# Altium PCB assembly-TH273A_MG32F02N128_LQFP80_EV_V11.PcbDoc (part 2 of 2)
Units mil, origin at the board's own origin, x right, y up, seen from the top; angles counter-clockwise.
Board outline 4724.41 x 2637.8 mil, 2 copper layers (Top Layer, Bottom Layer); 182 components, 166 nets, 741 pads, 331 vias.
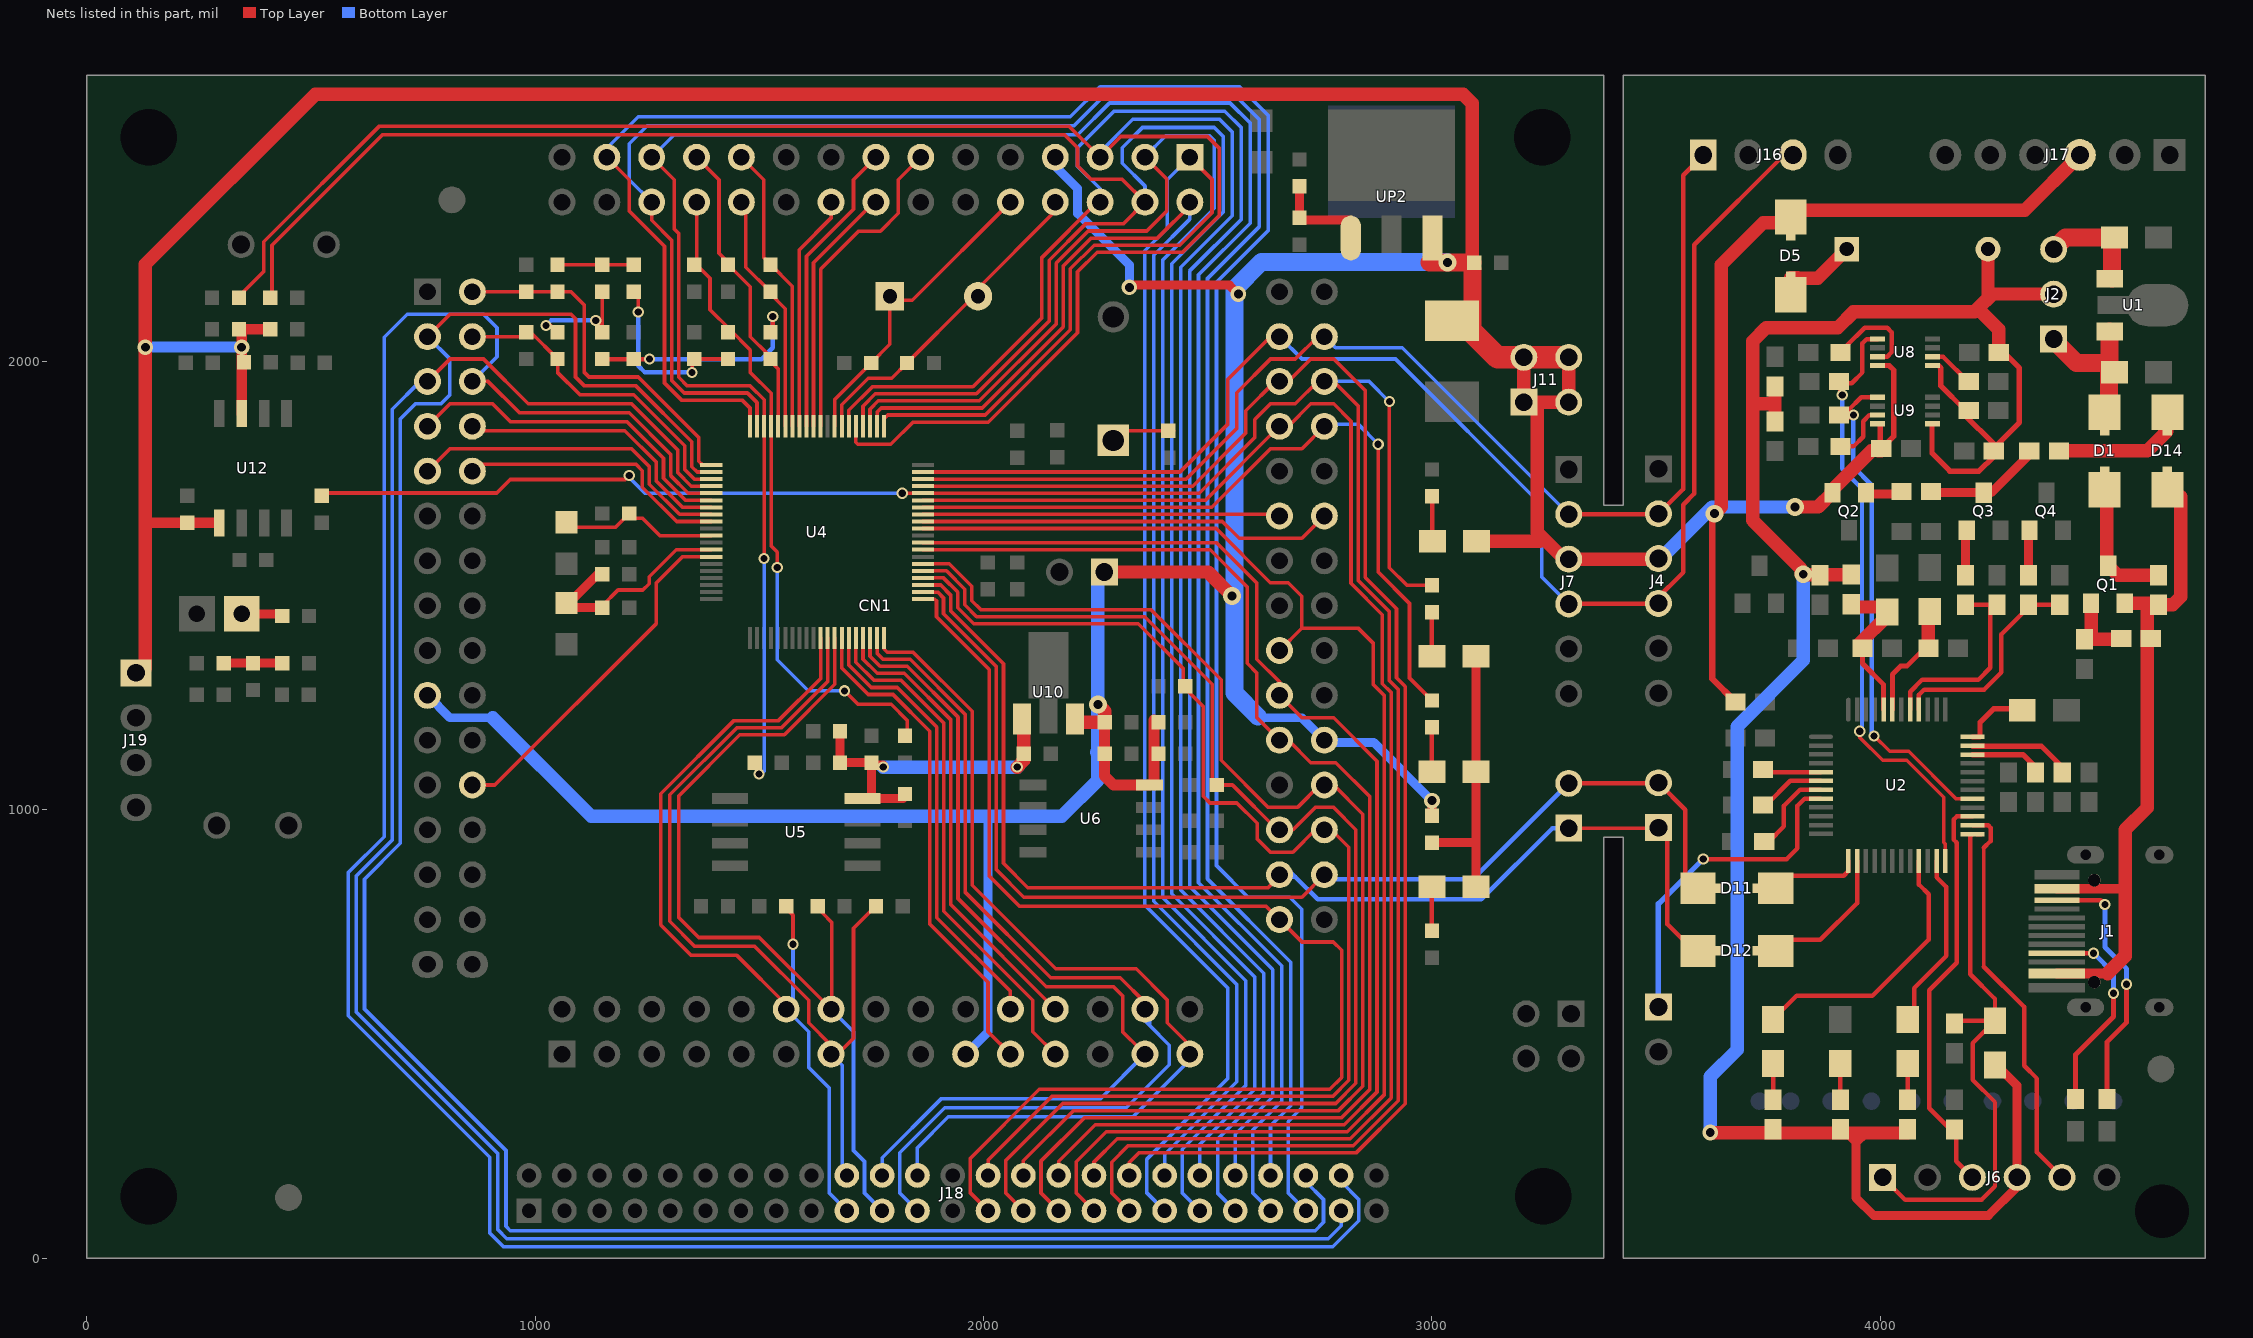
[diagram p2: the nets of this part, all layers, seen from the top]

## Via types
v1: diameter 20, hole 12, Top Layer to Bottom Layer, tented both sides, 236 vias
v2: diameter 25, hole 16, Top Layer to Bottom Layer, tented both sides, 57 vias
v3: diameter 30, hole 12, Top Layer to Bottom Layer, tented both sides, 13 vias
v4: diameter 35, hole 20, Top Layer to Bottom Layer, tented both sides, 8 vias
v5: diameter 40, hole 20, Top Layer to Bottom Layer, tented both sides, 7 vias
v6: diameter 25, hole 12, Top Layer to Bottom Layer, tented both sides, 6 vias
v7: diameter 30, hole 16, Top Layer to Bottom Layer, tented both sides, 2 vias
v8: diameter 28, hole 16, Top Layer to Bottom Layer, tented both sides, 1 vias
v9: diameter 15, hole 12, Top Layer to Bottom Layer, tented both sides, 1 vias

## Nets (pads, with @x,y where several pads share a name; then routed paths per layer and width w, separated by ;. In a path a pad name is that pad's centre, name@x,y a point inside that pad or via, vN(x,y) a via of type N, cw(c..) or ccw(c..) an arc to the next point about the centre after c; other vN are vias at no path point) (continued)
LCD_P16: CN1.12 J18.19 R52.1 U4.11 | length 1965.9
  Top Layer w8: R52.1@1552.42,777.5 1559.92,777.5 1562.42,777.5 1574.92,765 v2(1574.92,700) ; CN1.12@1559.92,565 1449.92,675 1347.91,675 1279.92,742.99 1279.92,1035.25 1443.43,1198.75 1542.83,1198.75 1636.54,1292.46 U4.11@1636.54,1382.91
  Bottom Layer w8: CN1.12@1574.92,560 1569.92,555 CN1.12@1559.92,555 ; v2(1574.92,700) 1574.92,570 CN1.12@1559.92,555 ; J18.19@1695.04,105.63 1655.67,145 1655.67,379.25 1609.92,425 1609.92,505 CN1.12@1559.92,555
LCD_P17: CN1.13 J18.20 R49.1 U4.12 | length 2044.5
  Top Layer w8: U4.12@1652.28,1382.91 1652.28,1285.93 1549.35,1183 1449.95,1183 1299.92,1032.98 1299.92,751.27 1356.2,695 1489.92,695 1609.92,575 1609.92,525 1659.92,475 CN1.13@1659.92,455 ; CN1.13@1674.92,455 1709.92,490 1709.92,735.41 1754.51,780 1759.92,780 1764.92,780 R49.1@1769.92,785
  Bottom Layer w8: CN1.13@1659.92,430.71 CN1.13@1659.92,455 1684.92,430 1684.92,194.49 J18.20@1695.04,184.37
LCD_P18: CN1.14 J18.21 R50.1 U4.13 | length 1979.7
  Top Layer w8: R50.1@1639.92,785 1639.92,770 1661.56,748.36 CN1.14@1661.56,556.64 ; CN1.14@1656.64,558.28 1499.92,715 1364.48,715 1319.92,759.56 1319.92,1030.71 1456.47,1167.26 1555.88,1167.26 1668.03,1279.41 U4.13@1668.03,1382.91
  Bottom Layer w8: CN1.14@1659.92,555 1709.92,505 1709.92,240 1734.41,215.51 1734.41,145 J18.21@1773.78,105.63
LCD_P19: CN1.27 J18.22 U4.18 | length 2013.1
  Top Layer w8: U4.18@1746.77,1382.91 1746.77,1342.1 1769.11,1319.76 1829.7,1319.76 1942.91,1206.55 1942.91,802.01 2139.92,605 2289.92,605 2309.92,585 2309.92,505 CN1.27@2350.36,464.56
  Bottom Layer w8: J18.22@1773.78,184.37 1773.78,223.86 1904.92,355 2259.92,355 CN1.27@2359.92,455
LCD_P20: CN1.28 J18.23 U4.19 | length 2176.1
  Top Layer w8: U4.19@1762.52,1382.91 1762.52,1348.62 1775.63,1335.51 1836.22,1335.51 1958.66,1213.07 1958.66,816.26 2149.92,625 2304.92,625 2359.92,570 CN1.28@2359.92,555
  Bottom Layer w8: J18.23@1852.52,105.63 1813.15,145 1813.15,234.94 1913.21,335 2318.11,335 2414.37,431.26 2414.37,475 2369.92,519.45 ; CN1.28@2359.92,529.45 2369.92,519.45 ; CN1.28@2369.92,545 2369.92,519.45
LCD_P21: CN1.29 J18.24 U4.20 | length 2093.6
  Top Layer w8: U4.20@1778.27,1382.91 1778.27,1357.87 1784.88,1351.26 1842.75,1351.26 1974.41,1219.6 1974.41,831.22 2160.63,645 2340.43,645 2409.92,575.51 2409.92,525 CN1.29@2459.92,475 ; CN1.29@2459.92,454.29 CN1.29@2459.92,455
  Bottom Layer w8: J18.24@1852.52,184.37 1852.52,246.16 1921.36,315 2333.11,315 2459.92,441.81 CN1.29@2459.92,455
LCD_P22: CN1.32 J18.27 U4.21 | length 2867.9
  Top Layer w8: U4.21@1864.88,1469.53 1891.1,1469.53 1894.92,1465.71 1894.92,1430.46 2012.87,1312.51 2012.87,852.05 2079.92,785 2629.92,785 CN1.32@2659.92,755 2709.92,705 2779.92,705 2798.62,686.3 2798.62,402.88 2772,376.26 2124.37,376.26 1970.63,222.52 1970.63,145 J18.27@2010,105.63
LCD_P23: CN1.35 J18.28 R47.1 U4.24 | length 2862.9
  Top Layer w8: U4.24@1864.88,1516.77 1910.67,1516.77 1942.17,1485.28 1942.17,1450.48 1977.89,1414.76 2345.16,1414.76 2445.13,1314.8 R47.1@2445.13,1275 ; J18.28@2010,184.37 2010,218.23 2152.28,360.51 2778.52,360.51 2814.37,396.36 2814.37,916.3 2775.67,955 CN1.35@2759.92,955 2739.92,955 2689.92,905 2639.92,905 2610.33,934.59 2610.33,969.59 2564.92,1015 2504.92,1015 2489.92,1030 2489.92,1230.2 2447.52,1272.6 R47.1@2445.13,1275 ; R47.1@2445.13,1284.8 R47.1@2445.13,1275
LCD_P24: CN1.36 J18.29 R46.1 U4.25 | length 2938.9
  Top Layer w8: U4.25@1864.88,1532.52 1917.19,1532.52 1957.91,1491.8 1957.91,1457.01 1984.41,1430.51 2359.41,1430.51 2509.92,1280 2509.92,1055 R46.1@2519.92,1055 ; J18.29@2088.74,105.63 2049.37,145 2049.37,217.6 2176.54,344.76 2785.05,344.76 2830.12,389.83 2830.12,955.51 2780.63,1005 2739.92,1005 2689.92,955 CN1.36@2659.92,955 2654.92,955 2554.92,1055 R46.1@2524.92,1055
LCD_P25: CN1.37 J18.30 U4.26 | length 2842.7
  Top Layer w8: U4.26@1864.88,1548.27 1923.72,1548.27 1973.66,1498.32 1973.66,1466.26 1993.66,1446.26 2373.15,1446.26 2529.92,1289.49 2529.92,1110 2634.92,1005 2699.92,1005 2749.92,1055 CN1.37@2759.92,1055 2780.63,1055 2845.87,989.76 2845.87,383.31 2791.57,329.02 2200.79,329.02 2088.74,216.97 J18.30@2088.74,184.37
LCD_P26: CN1.40 J18.31 U4.28 | length 2962.2
  Top Layer w8: U4.28@1864.88,1579.76 2505.16,1579.76 2588.16,1496.76 2588.16,1326.25 2609.41,1305 2609.41,1205.51 CN1.40@2659.92,1155 2679.92,1155 2729.92,1105 2785.63,1105 2861.61,1029.02 2861.61,376.79 2798.09,313.27 2225.04,313.27 2128.11,216.34 2128.11,145 J18.31@2167.48,105.63
LCD_P27: CN1.42 J18.32 U4.29 | length 2874.7
  Top Layer w8: U4.29@1864.88,1595.51 2519.41,1595.51 2609.37,1505.55 2609.37,1335.55 2659.92,1285 CN1.42@2659.92,1255 2709.92,1205 2780.63,1205 2877.36,1108.27 2877.36,370.27 2804.62,297.52 2249.29,297.52 2167.48,215.71 J18.32@2167.48,184.37
LCD_P28: CN1.44 J18.33 U4.31 | length 3113.4
  Top Layer w8: U4.31@1864.88,1627.01 2518.62,1627.01 2639.37,1506.26 2679.37,1506.26 2709.37,1476.26 2709.37,1404.45 ; J18.33@2246.22,105.63 2206.85,145 2206.85,215.08 2273.54,281.77 2811.14,281.77 2893.11,363.74 2893.11,1255 2869.37,1278.74 2869.37,1370.55 2834.92,1405 2709.92,1405 2709.37,1404.45 ; CN1.44@2659.92,1355 2709.37,1404.45
LCD_P29: CN1.54 J18.34 U4.35 | length 3357.6
  Top Layer w8: U4.35@1864.88,1690 2494.92,1690 2657.42,1852.5 2659.92,1852.5 2662.42,1852.5 2664.92,1855 2679.92,1855 2729.92,1905 2780.63,1905 2819.37,1866.26 2819.37,1504.92 2889.37,1434.92 2889.37,1281.01 2908.86,1261.52 2908.86,357.22 2817.66,266.02 2297.79,266.02 2246.22,214.45 J18.34@2246.22,184.37
LCD_P30: CN1.55 J18.35 R55.1 R91.1 U4.36 | length 5578.2
  Top Layer w8: R91.1@524.41,1706.26 914.37,1706.26 944.37,1736.26 1201.12,1736.26 v2(1209.86,1745) ; v2(1818.66,1705.75) U4.36@1864.88,1705.75 2480.67,1705.75 2604.92,1830 2604.92,1870 2639.92,1905 2694.92,1905 2744.92,1955 CN1.55@2759.92,1955 2780.63,1955 2835.12,1900.51 2835.12,1511.44 2905.12,1441.44 2905.12,1335 2905.12,1287.53 2924.61,1268.04 2924.61,350.7 2824.19,250.28 2322.05,250.28 2285.59,213.82 2285.59,145 J18.35@2324.96,105.63 ; v2(2904.92,1910) 2904.92,1539.49 2944.09,1500.32 R55.1@2999.96,1500.32 2958.39,1500.32
  Bottom Layer w8: v2@1214.41,1736.26 1244.92,1705.75 v2(1818.66,1705.75) ; CN1.55@2759.92,1955 2859.92,1955 v2(2904.92,1910)
LCD_P31: CN1.56 J18.36 U4.37 | length 3487.9
  Top Layer w8: U4.37@1864.88,1721.5 2466.42,1721.5 2584.92,1840 2584.92,1890 2649.92,1955 CN1.56@2659.92,1955 2679.72,1955 2729.72,2005 2780.63,2005 2850.87,1934.76 2850.87,1517.96 2920.87,1447.97 2920.87,1294.06 2940.35,1274.57 2940.35,344.17 2830.71,234.53 2346.3,234.53 2324.96,213.19 J18.36@2324.96,184.37
LCD_P32: CN1.61 J18.37 U4.41 | length 3720.9
  Top Layer w8: U4.41@1778.27,1855.35 1778.27,1872.16 1786.21,1880.1 2003.67,1880.1 2193.62,2070.05 2193.62,2205.97 2246.67,2259.02 2437.13,2259.02 2509.37,2331.26 2509.37,2405.55 CN1.61@2459.92,2455
  Bottom Layer w8: J18.37@2403.7,105.63 2364.33,145 2364.33,220.83 2544.92,401.42 2544.92,602.01 2359.37,787.56 2359.37,2246.26 2409.37,2296.26 2409.37,2404.45 CN1.61@2459.92,2455
LCD_P33: CN1.62 J18.38 U4.42 | length 3352.1
  Top Layer w8: U4.42@1762.52,1855.35 1762.52,1886.63 1771.74,1895.85 1997.15,1895.85 2177.87,2076.58 2177.87,2212.49 2240.14,2274.76 2387.87,2274.76 CN1.62@2464.02,2350.91
  Bottom Layer w8: J18.38@2403.7,184.37 2403.7,231.92 2564.92,393.14 2564.92,610.29 2379.37,795.85 2379.37,2236.26 2459.37,2316.26 CN1.62@2459.37,2355
LCD_P34: CN1.63 J18.39 U4.43 | length 3866.6
  Top Layer w8: U4.43@1746.77,1855.35 1746.77,1893.15 1765.22,1911.6 1990.62,1911.6 2162.13,2083.1 2162.13,2219.02 2233.62,2290.51 2363.62,2290.51 2408.37,2335.26 2408.37,2406.55 CN1.63@2359.92,2455
  Bottom Layer w8: CN1.63@2359.92,2456.74 2406.18,2503 2504.37,2503 2514.37,2493 2514.37,2340.97 2399.37,2225.97 2399.37,804.13 2584.92,618.58 2584.92,384.85 2443.07,243 2443.07,145 J18.39@2482.44,105.63
LCD_P35: CN1.64 J18.40 R89.1 U4.44 | length 6092.7
  Top Layer w8: R89.1@413.15,2141.26 413.15,2258.74 659.41,2505 2180.63,2505 2209.37,2476.26 2209.37,2436.26 2239.37,2406.26 2308.66,2406.26 CN1.64@2359.92,2355 2311.18,2306.26 2227.1,2306.26 2146.38,2225.54 2146.38,2089.62 1984.1,1927.35 1758.7,1927.35 1731.02,1899.67 U4.44@1731.02,1855.35
  Bottom Layer w8: CN1.64@2359.92,2341.81 CN1.64@2359.92,2355 2359.92,2390.71 2309.37,2441.26 2309.37,2476.26 2354.37,2521.26 2514.37,2521.26 2534.37,2501.26 2534.37,2332.68 2419.37,2217.68 2419.37,812.41 2604.92,626.86 2604.92,376.57 2482.44,254.09 J18.40@2482.44,184.37
LCD_P36: CN1.65 J18.41 R90.1 U4.45 | length 6737.5
  Top Layer w8: R90.1@337.52,2143.11 R90.1@339.37,2144.96 ; R90.1@339.37,2141.26 R90.1@339.37,2144.96 ; U4.45@1715.28,1855.35 1715.28,1819.65 1719.92,1815 1793.11,1815 1842.47,1864.36 2010.19,1864.36 2209.37,2063.53 2209.37,2199.45 2253.19,2243.27 2443.65,2243.27 2525.12,2324.74 2525.12,2475.55 2499.41,2501.26 2389.37,2501.26 ; 2324.37,2501.26 2389.37,2501.26 ; R90.1@339.37,2144.96 394.41,2200 394.41,2266.5 651.65,2523.74 2191.18,2523.74 CN1.65@2259.92,2455 2306.18,2501.26 2389.37,2501.26
  Bottom Layer w8: CN1.65@2259.92,2455 2259.92,2466.81 2332.63,2539.52 2526.11,2539.52 2554.37,2511.26 2554.37,2324.4 2439.37,2209.4 2439.37,820.7 2624.92,635.15 2624.92,368.28 2521.81,265.17 2521.81,145 J18.41@2561.18,105.63
LCD_P37: CN1.66 J18.42 U4.46 | length 3918.9
  Top Layer w8: U4.46@1699.53,1855.35 1699.53,1890.45 1752.18,1943.1 1976.21,1943.1 2130.12,2097.01 2130.12,2231.55 2253.57,2355 CN1.66@2259.92,2355
  Bottom Layer w8: CN1.66@2259.92,2355 2259.92,2385 2209.37,2435.55 2209.37,2476.26 2290.89,2557.78 2537.85,2557.78 2574.37,2521.26 2574.37,2316.11 2459.37,2201.11 2459.37,828.98 2644.92,643.43 2644.92,360 2561.18,276.26 J18.42@2561.18,184.37
LCD_P38: CN1.85 J18.43 R53.1 U4.58 | length 5585.5
  Top Layer w8: CN1.85@1259.92,2455 1309.92,2405 1309.92,2295 1319.92,2285 1319.92,1964.41 1339.33,1945 1479.92,1945 1510.55,1914.37 U4.58@1510.55,1855.35 v2(1510.55,1560) ; v2@1494.41,1079.41 R53.1@1494.41,1104.41
  Bottom Layer w8: CN1.85@1259.92,2455 1309.92,2505 2209.92,2505 2280.96,2576.04 2549.59,2576.04 2594.37,2531.26 2594.37,2307.83 2479.37,2192.83 2479.37,837.27 2664.92,651.72 2664.92,350 2600.55,285.63 2600.55,145 J18.43@2639.92,105.63 ; v2@1504.41,1079.41 1510.55,1085.55 v2(1510.55,1560)
  other v2: 1499.41,1079.41
LCD_P39: CN1.86 J18.44 U4.59 | length 4930.7
  Top Layer w8: CN1.86@1259.92,2355 1259.92,2314.25 1304.17,2270 1304.17,1957.88 1332.81,1929.25 1473.4,1929.25 1494.8,1907.85 U4.59@1494.8,1855.35
  Bottom Layer w8: CN1.86@1259.92,2355 1209.92,2405 1209.92,2485 1249.92,2525 1419.92,2525 ; 1289.92,2525 1419.92,2525 ; J18.44@2639.92,184.37 2639.92,295 2684.92,340 2684.92,660 2499.37,845.55 2499.37,2184.54 2614.37,2299.54 2614.37,2539.54 2559.61,2594.3 2270.94,2594.3 2201.64,2525 1419.92,2525
LCD_P40: CN1.87 J18.45 U4.60 | length 5071.3
  Top Layer w8: CN1.87@1159.92,2455 1209.92,2405 1209.92,2335 1288.43,2256.5 1288.43,1951.36 1326.28,1913.5 1461.42,1913.5 1479.05,1895.87 U4.60@1479.05,1855.35
  Bottom Layer w8: CN1.87@1159.92,2455 1159.92,2475 1229.92,2545 1299.92,2545 ; 1289.92,2545 1299.92,2545 ; J18.45@2704.92,119.37 J18.45@2718.66,105.63 2679.29,145 2679.29,304.43 2709.86,335 2709.86,778 2682.86,805 2589.86,805 2519.37,875.49 2519.37,2176.26 2634.37,2291.26 2634.37,2548.61 2570.42,2612.56 2260.91,2612.56 2193.35,2545 1299.92,2545
LCD_P41: CN1.93 J18.46 U4.62 | length 5097
  Top Layer w8: CN1.93@759.92,2055 809.92,2105 1079.92,2105 1089.92,2095 1089.92,1965 1109.92,1945 1224.92,1945 1349.17,1820.75 1349.17,1764.99 1361.17,1752.99 U4.62@1392.44,1752.99
  Bottom Layer w8: CN1.93@759.92,2055 809.92,2005 809.92,1925 789.92,1905 733.11,1905 699.37,1871.26 699.37,924.96 619.37,844.96 619.37,555.55 934.92,240 934.92,70.71 944.37,61.26 2739.37,61.26 2758.03,79.92 2758.03,130.72 J18.46@2718.66,170.09
LCD_P42: CN1.95 J18.47 U4.64 | length 4832.2
  Top Layer w8: CN1.95@759.92,1955 809.92,2005 884.92,2005 984.92,1905 1214.92,1905 1317.68,1802.24 1317.68,1751.94 1348.12,1721.5 U4.64@1392.44,1721.5
  Bottom Layer w8: CN1.95@759.92,1955 743.11,1955 681.37,1893.26 681.37,932.42 601.37,852.42 601.37,548.1 916.92,232.54 916.92,63.25 936.91,43.26 2768.32,43.26 2797.4,72.35 J18.47@2797.4,105.63
LCD_P43: CN1.96 J18.48 U4.65 | length 5330.8
  Top Layer w8: CN1.96@859.92,1955 894.92,1955 964.92,1885 1209.92,1885 1301.93,1792.99 1301.93,1745.42 1341.6,1705.75 U4.65@1392.44,1705.75
  Bottom Layer w8: CN1.96@859.92,1955 914.92,2010 914.92,2075 884.92,2105 714.92,2105 663.37,2053.45 663.37,939.87 583.37,859.87 583.37,540.64 898.92,225.09 898.92,55.8 929.46,25.26 2778.6,25.26 2836.77,83.43 2836.77,130.72 J18.48@2797.4,170.09
LCD_V1: R80.1 R81.2 R100.2 | length 396.2
  Top Layer w8: v2(1229.92,2110) R80.1@1229.92,2150 ; v2(1349.92,1975) R81.2@1349.92,2000 ; R81.2@1354.92,2005 R100.2@1429.92,2005 R100.2@1439.92,2005
  Bottom Layer w10: v2(1229.92,2110) 1229.92,1990 1244.92,1975 v2(1349.92,1975)
LCD_V2: R79.1 R80.2 R99.2 | length 180
  Top Layer w8: R99.2@1049.92,2215 R79.1@1149.92,2215 R80.2@1219.92,2215 R80.2@1229.92,2215
LCD_V3: R78.1 R79.2 R98.2 | length 258.2
  Top Layer w8: v2(1024.33,2080) 1034.92,2080 R98.2@1049.92,2065 ; v2(1134.92,2091) R78.1@1149.92,2076 ; R78.1@1149.92,2065 R78.1@1149.92,2076 ; R79.2@1149.92,2155 1149.92,2091 R78.1@1149.92,2076
  Bottom Layer w10: v2(1024.33,2080) 1035.33,2091 v2(1134.92,2091)
LCD_VT: R33.1 R78.2 R97.2 | length 497.4
  Top Layer w10: R78.2@1149.92,2005 R33.1@1219.92,2005 v2(1254.92,2005) ; R97.2@1524.92,2065 1529.92,2070 v2(1529.92,2100)
  Bottom Layer w10: v2(1254.92,2005) 1504.92,2005 1529.92,2030 v2(1529.92,2100)
MG_PA0: CN1.114 U4.74 | length 796.3
  Top Layer w8: CN1.114@859.92,1055 910,1055 1270.39,1415.4 1270.39,1505.86 1328.55,1564.02 U4.74@1392.44,1564.02
MG_PB8(TX): CN1.33 D11.2 J5.2 J15.2 U4.22 | length 2596.8
  Top Layer w8: U4.22@1864.88,1485.28 1897.63,1485.28 1910.67,1472.23 1910.67,1436.98 2028.62,1319.03 2028.62,866.3 2089.92,805 2709.92,805 CN1.33@2759.92,855
  Top Layer w10: J15.2@3304.96,1058.74 J5.2@3504.96,1058.74 ; J5.2@3504.96,1060 3564.96,1000 3564.96,825 D11.2@3564.96,810
  Bottom Layer w10: CN1.33@2754.96,845 2759.92,845 3091.22,845 J15.2@3304.96,1058.74
MG_PB9(RX): CN1.34 D12.1 J5.1 J15.1 U4.23 | length 2593.9
  Top Layer w8: U4.23@1864.88,1501.02 1904.15,1501.02 1926.42,1478.75 1926.42,1443.5 2044.37,1325.55 2044.37,880.55 2098.85,826.07 2634.18,826.07 CN1.34@2659.92,851.81 ; J15.1@3304.96,958.74 J5.1@3504.96,958.74 ; J5.1@3504.96,960 J5.1@3510.73,954.23
  Top Layer w10: J5.1@3524.96,958 3524.96,745 D12.1@3578.35,691.61
  Bottom Layer w10: CN1.34@2674.92,850 2694.92,850 ; CN1.34@2684.92,860 2694.92,850 ; J15.1@3304.96,958.74 3268.66,958.74 3109.92,800 2744.92,800 2694.92,850
MG_PC0: CN1.53 R54.1 U4.34 | length 1729.8
  Top Layer w8: U4.34@1864.88,1674.25 2509.17,1674.25 2639.92,1805 2709.92,1805 CN1.53@2759.92,1855 ; v2(2879.92,1815) 2879.92,1530 2949.92,1460 2949.92,1293.5 R54.1@2999.96,1243.46
  Bottom Layer w8: CN1.53@2759.92,1860 2834.92,1860 v2(2879.92,1815)
MG_PD0: C66.1 CN1.81 U4.54 | length 646.7
  Top Layer w8: CN1.81@1459.92,2455 1509.92,2405 1509.92,2231.22 1525.53,2215.61 1573.54,2167.6 U4.54@1573.54,1855.35
MG_PD1: C66.2 CN1.82 U4.55 | length 540.2
  Top Layer w8: CN1.82@1459.92,2355 1469.92,2345 1469.92,2210 1522.42,2157.5 1522.42,2155 1522.42,2152.5 1557.8,2117.13 U4.55@1557.8,1855.35
MG_PD2: C62.1 CN1.83 R97.1 U4.56 | length 675.1
  Top Layer w8: CN1.83@1359.92,2455 1409.92,2405 1409.92,2241 1432.92,2218 1432.92,2215 1432.92,2213 1479.92,2166 1479.92,2055 1519.92,2015 1519.92,2005 1522.42,2002.5 1542.05,1982.87 U4.56@1542.05,1855.35
MG_PD3: C65.1 CN1.84 R51.1 R100.1 U4.57 | length 1528.9
  Top Layer w8: C65.1@1357.42,2217.5 C65.1@1359.92,2215 ; 1359.92,2305 CN1.84@1359.92,2355 C65.1@1359.92,2215 ; v2(1539.92,1540) 1539.92,1574.49 1526.3,1588.11 U4.57@1526.3,1855.35 1526.3,1928.62 1479.92,1975 1479.92,2025 1434.92,2070 1389.92,2115 1389.92,2185 C65.1@1359.92,2215 ; v2(1689.92,1265) 1719.92,1235 1794.01,1235 1829.92,1199.08 R51.1@1829.92,1165
  Bottom Layer w8: v2(1539.92,1540) 1539.92,1334.2 1609.12,1265 v2(1689.92,1265)
MG_PD7: C64.1 CN1.92 R99.1 U4.61 | length 811.4
  Top Layer w8: CN1.92@859.92,2155 C64.1@979.92,2155 R99.1@1049.92,2155 1079.92,2155 1109.92,2125 1109.92,1975 1119.92,1965 1229.92,1965 1364.92,1830 1364.92,1776.97 1373.15,1768.74 U4.61@1392.44,1768.74
MG_PD9: C63.1 CN1.94 R98.1 U4.63 | length 726.8
  Top Layer w8: CN1.94@859.92,2055 979.92,2055 999.92,2055 ; C63.1@989.92,2065 R98.1@1049.92,2005 1049.92,1975 1099.92,1925 1219.77,1925 1333.43,1811.34 1333.43,1758.46 1354.65,1737.24 U4.63@1392.44,1737.24
MG_PD12: CN1.97 U4.66 | length 768.6
  Top Layer w8: CN1.97@759.92,1855 809.92,1905 904.92,1905 944.92,1865 1204.92,1865 1286.18,1783.74 1286.18,1738.9 1335.08,1690 U4.66@1392.44,1690
MG_PD13: CN1.98 U4.67 | length 632.1
  Top Layer w8: CN1.98@859.92,1855 869.92,1845 1199.92,1845 1270.43,1774.49 1270.43,1732.37 1328.55,1674.25 U4.67@1392.44,1674.25
MG_PD14: CN1.99 U4.68 | length 737
  Top Layer w8: CN1.99@759.92,1755 809.92,1805 1214.92,1805 1254.69,1765.24 1254.69,1725.85 1322.03,1658.5 U4.68@1392.44,1658.5
MG_PD15: CN1.100 U4.69 | length 608.8
  Top Layer w8: CN1.100@859.92,1765 864.92,1770 1224.92,1770 1238.94,1755.98 1238.94,1719.33 1315.51,1642.76 U4.69@1392.44,1642.76
MG_PE0: CN1.21 U4.14 | length 1116
  Top Layer w8: U4.14@1683.78,1382.91 1683.78,1316.01 1743.01,1256.77 1798.15,1256.77 1879.92,1175 1879.92,745 2009.88,615.04 2009.88,505.04 CN1.21@2059.92,455
MG_PE1: CN1.22 U4.15 | length 1011.1
  Top Layer w8: U4.15@1699.53,1382.91 1699.53,1322.53 1749.54,1272.52 1807.4,1272.52 1895.67,1184.25 1895.67,759.25 2059.92,595 CN1.22@2059.92,555
MG_PE2: CN1.23 U4.16 | length 1147.6
  Top Layer w8: U4.16@1715.28,1382.91 1715.28,1329.05 1756.06,1288.27 1816.65,1288.27 1911.42,1193.5 1911.42,773.5 2109.88,575.04 2109.88,505.04 CN1.23@2159.92,455
MG_PE3: CN1.24 U4.17 | length 1041.1
  Top Layer w8: U4.17@1731.02,1382.91 1731.02,1335.58 1762.58,1304.02 1823.18,1304.02 1927.17,1200.03 1927.17,787.76 CN1.24@2159.92,555
MG_PE8: CN1.49 U4.32 | length 931.4
  Top Layer w8: U4.32@1864.88,1642.76 2532.17,1642.76 2569.92,1605 2709.92,1605 CN1.49@2759.92,1655
MG_PE9: CN1.50 U4.33 | length 781.5
  Top Layer w8: U4.33@1864.88,1658.5 CN1.50@2646.42,1658.5
MG_PE12: CN1.73 U4.50 | length 720.9
  Top Layer w8: U4.50@1636.54,1855.35 1636.54,2205.61 1720.92,2290 1769.92,2290 1809.92,2330 1809.92,2405 CN1.73@1859.92,2455
MG_PE13: CN1.76 U4.51 | length 559.6
  Top Layer w8: U4.51@1620.79,1855.35 1620.79,2219.87 1755.92,2355 CN1.76@1759.92,2355
MG_PE14: CN1.75 U4.52 | length 663.8
  Top Layer w8: U4.52@1605.04,1855.35 1605.04,2234.12 1709.92,2339 1709.92,2405 CN1.75@1759.92,2455
MG_PE15: CN1.78 U4.53 | length 528.9
  Top Layer w8: U4.53@1589.29,1855.35 1589.29,2248.91 1659.92,2319.54 CN1.78@1659.92,2355
MG_VCAP: C60.1 C70.1 U4.71 | length 351.3
  Top Layer w8: C60.1@1069.92,1630 1179.28,1630 C70.1@1209.92,1660.64 ; C70.1@1209.92,1650 1239.41,1650 1278.15,1611.26 U4.71@1392.44,1611.26
MG_VREF: C48.1 C71.1 R73.1 U4.73 | length 496.7
  Top Layer w8: R73.1@1144.92,1515 1144.92,1525 R73.1@1144.92,1530 ; C71.1@1149.92,1455 1184.92,1490 1239.92,1490 1254.07,1504.15 1254.07,1519.15 1314.68,1579.76 U4.73@1392.44,1579.76
  Top Layer w20: C48.1@1074.92,1450.64 1145.56,1450.64 1147.74,1452.82 C71.1@1149.92,1455 ; C48.1@1074.92,1460 1139.92,1525 1144.92,1525 R73.1@1149.92,1525
NetC2_2: C2.2 Q1.1 R5.2 | length 165
  Top Layer w30: R5.2@4454.96,1380 R5.2@4469.96,1380 ; Q1.1@4469.96,1460 R5.2@4469.96,1380 ; C2.2@4539.96,1380 4536.92,1380 R5.2@4469.96,1380
NetC6_1: C6.1 C7.2 R10.2 U2.44 | length 332.7
  Top Layer w11: C7.2@3959.92,1360 3959.92,1326 4007.15,1278.77 U2.44@4007.15,1223.13
  Top Layer w30: R10.2@3949.96,1452 4014.92,1452 C6.1@4014.92,1440.79 4014.92,1432 3953.92,1371 C7.2@3953.92,1366
NetC8_2: C8.2 C9.1 U2.43 | length 251
  Top Layer w11: U2.43@4026.84,1223.13 4026.84,1301.92 4044.92,1320 4058.92,1320 4095.42,1356.5 4106.92,1356.5 C8.2@4110.42,1356.5
  Top Layer w30: C8.2@4106.92,1360 C9.1@4106.92,1426.05
NetC11_1: C11.1 U2.36 | length 149.7
  Top Layer w12: U2.36@4205.42,1162.16 4222.12,1162.16 4222.12,1194.68 4252.82,1225.39 C11.1@4309.86,1225.39
NetC52_1: C52.1 R84.2 R88.1 | length 130
  Top Layer w20: R88.1@305.63,1326.81 C52.1@370.63,1326.81 R84.2@435.63,1326.81
NetD1_1: D1.1 Q1.3 R1.2 | length 276.4
  Top Layer w30: D1.1@4504.92,1698.39 4504.92,1546.98 Q1.3@4507.96,1543.94 4528.9,1523 R1.2@4619.96,1523
NetD2_1: D2.1 R6.2 | length 80.8
  Top Layer w10: R6.2@3760.51,353.26 D2.1@3760.51,434.05
NetD3_1: D3.1 R9.2 | length 80.8
  Top Layer w10: R9.2@4060.51,353.26 D3.1@4060.51,434.05
NetD4_1: D4.1 R11.2 | length 80.8
  Top Layer w10: R11.2@3910.51,353.26 D4.1@3910.51,434.05
NetD5_1: D5.1 SW1.1 | length 154.2
  Top Layer w30: D5.1@3799.92,2185.93 3815.85,2185.93 3814.92,2185 3859.96,2185 SW1.1@3924.96,2250
NetD8_1: D8.1 D9.1 D10.1 R58.1 | length 609.3
  Top Layer w20: R58.1@2999.96,926.61 3095.51,926.61 ; D10.1@3098.39,828.19 D8.1@3098.39,1085.04 D9.1@3098.39,1341.89
NetD8_2: D8.2 R54.2 | length 98.4
  Top Layer w10: D8.2@2999.96,1085.04 R54.2@2999.96,1183.46
NetD9_2: D9.2 R55.2 | length 98.4
  Top Layer w10: D9.2@2999.96,1341.89 R55.2@2999.96,1440.32
NetD10_2: D10.2 R56.2 | length 98.4
  Top Layer w10: R56.2@2999.96,729.76 D10.2@2999.96,828.19
NetD11_1: D11.1 U2.13 | length 188.6
  Top Layer w10: D11.1@3766.57,852.74 3917.96,852.74 3928.41,863.19 U2.13@3928.41,885.65
NetD12_2: D12.2 U2.14 | length 296
  Top Layer w10: D12.2@3779.96,709.74 3866.06,709.74 3948.1,791.78 U2.14@3948.1,885.65
NetD13_2: D13.2 R43.2 | length 100.3
  Top Layer w8: D13.2@2999.96,1599.53 D13.2@3000.75,1598.74
  Top Layer w10: D13.2@3000.75,1598.74 R43.2@3000.75,1697.95
NetD14_2: D14.2 R17.1 | length 272.5
  Top Layer w30: R17.1@4397.92,1800 4594.92,1800 D14.2@4639,1844.07 ; D14.2@4628.07,1868.15 D14.2@4639.92,1868.15 ; D14.2@4634,1844.07 D14.2@4634.92,1845
NetJ1_A5: J1.A5 R26.1 | length 460.3
  Top Layer w11: J1.A5@4393.76,679.9 v2(4475.51,679.9) ; R26.1@4434.96,354.74 4434.96,453.74 4519.96,538.74 v2@4519.96,590.74
  Bottom Layer w11: v2(4475.51,679.9) 4519.51,635.9 v2(4519.51,590.74)
NetJ1_B5: J1.B5 R27.2 | length 582.9
  Top Layer w11: J1.B5@4393.76,798.01 4491.24,798.01 v2(4500.51,788.74) ; R27.2@4504.96,354.74 4504.96,481.74 4548.96,525.74 v2(4548.96,610.74)
  Bottom Layer w11: v2(4500.51,788.74) 4500.51,693.74 4548.96,645.29 v2(4548.96,610.74)
NetJP2_1: JP2.1 R85.2 | length 90
  Top Layer w20: JP2.1@345.63,1436.81 R85.2@435.63,1436.81
NetQ2_1: Q2.1 R18.2 | length 72
  Top Layer w20: Q2.1@3967.92,1703.94 R18.2@4039.92,1703.94
NetQ3_1: Q3.1 R19.2 | length 97.5
  Top Layer w20: R19.2@4189.96,1523 Q3.1@4189.96,1620.53
NetQ3_2: Q3.2 R17.2 R18.1 | length 242.2
  Top Layer w20: R18.1@4132.95,1706.97 Q3.2@4230.46,1706.97 4246.89,1706.97 4331.92,1792 R17.2@4331.92,1800
NetQ4_1: Q4.1 R23.2 | length 97.5
  Top Layer w20: R23.2@4329.96,1523 Q4.1@4329.96,1620.53
NetR15_1: R15.1 U2.35 | length 263.6
  Top Layer w12: U2.35@4205.42,1141.47 4234.96,1141.47 ; 4267.22,1141.47 4234.96,1141.47 ; R15.1@4405.51,1083 4405.51,1095 4359.04,1141.47 4234.96,1141.47
NetR16_1: R16.1 U2.34 | length 163.6
  Top Layer w12: U2.34@4205.42,1122.79 4317.72,1122.79 4345.51,1095 R16.1@4345.51,1083
NetR29_2: R29.2 U8.7 | length 202.9
  Top Layer w10: R29.2@3924.92,2035 3964.92,2075 4014.92,2075 4024.92,2065 4024.92,2020 4015.08,2010.16 U8.7@3993.9,2010.16 U8.7@3991.78,2010.16
NetR30_2: R30.2 U9.7 | length 132.5
  Top Layer w10: R30.2@3910.92,1810 3939.92,1810 3961.42,1831.5 3961.42,1866.5 3975.08,1880.16 U9.7@3993.9,1880.16
NetR64_2: R64.2 U8.2 | length 108.2
  Top Layer w10: U8.2@4115.94,2010.16 4139.76,2010.16 R64.2@4195.92,1954 ; R64.2@4183.42,1968.5 R64.2@4186.92,1965
NetR94_2: R94.2 R95.1 UP2.1 | length 170
  Top Layer w20: R95.1@2704.41,2320 R94.2@2704.41,2375 ; R95.1@2709.41,2315 R95.1@2709.92,2315 ; R95.1@2709.92,2320 R95.1@2709.92,2315 ; UP2.1@2818.41,2315 R95.1@2709.92,2315 ; UP2.1@2818.92,2305 UP2.1@2819.92,2305
NetR96_2: R96.2 SW2.1 | length 134.4
  Top Layer w8: SW2.1@2289.92,1845 R96.2@2411.92,1845 R96.2@2424.37,1845
P44: J6.5 U2.26 | length 900.8
  Top Layer w8: 4230.51,650 4230.51,915
  Top Layer w10: U2.26@4205.42,965.31 4240.2,965.31 4245.51,960 4245.51,930 4230.51,915 ; 4230.51,650 4320.51,560 4320.51,429 4349.06,400.45 4349.06,235.9 J6.5@4404.96,180
P45: J6.3 R25.1 U2.27 | length 931.6
  Top Layer w10: R25.1@4169.24,290.72 4169.24,287 4169.24,215.72 J6.3@4204.96,180 ; R25.1@4170.51,292 4165.51,292 4150.95,292 4108.96,333.99 4108.96,597.19 4170.51,658.74 4170.51,926 4163.92,932.59 4163.92,978.41 4170.5,984.99 U2.27@4205.42,984.99 ; J6.3@4206.24,181.28 J6.3@4213.51,174
PA13_SWDIO: CN1.58 J4.4 J7.4 J16.3 U4.39 | length 3281.4
  Top Layer w8: U4.39@1864.88,1752.99 2437.91,1752.99 2544.92,1860 2544.92,1960 2639.92,2055 CN1.58@2659.92,2055
  Top Layer w10: J7.4@3304.96,1458.74 J4.4@3489.96,1458.74 ; J4.4@3497.96,1467 3559.96,1529 3559.96,1680 3584.96,1705 3584.96,2260.04 3784.92,2460 J16.3@3804.96,2460
  Bottom Layer w8: CN1.58@2659.92,2055 2709.92,2005 2918.7,2005 3244.96,1678.74 3244.96,1518.74 J7.4@3304.96,1458.74
PA14_SWCLK: CN1.57 J4.2 J7.2 J16.1 U4.38 | length 2824.1
  Top Layer w8: U4.38@1864.88,1737.24 2452.17,1737.24 2564.92,1850 2564.92,1930 2639.92,2005 2694.92,2005 2744.92,2055 CN1.57@2759.92,2055
  Top Layer w10: J7.2@3304.96,1658.74 J4.2@3504.96,1658.74 ; J4.2@3504.96,1660 3559.96,1715 3559.96,2415 J16.1@3604.96,2460
  Bottom Layer w8: CN1.57@2759.92,2055 2784.92,2030 2933.7,2030 J7.2@3304.96,1658.74
PASS: D3.2 U2.23 | length 394.2
  Top Layer w10: D3.2@4075.51,530 4075.51,532.47 4075.51,602.29 4146.96,673.74 4146.96,827.74 4125.26,849.44 U2.23@4125.26,885.65
RST: C12.2 J6.1 R22.2 U2.25 | length 1228.1
  Top Layer w10: J6.1@4004.96,180 4054.96,130 4225.51,130 4255.51,160 4255.51,348 4205.51,398 4205.51,479.21 C12.2@4255.51,529.21 ; R22.2@4171.72,529.21 C12.2@4255.51,529.21 ; U2.25@4205.51,945 4200.51,940 4200.51,633 4255.51,578 C12.2@4255.51,529.21 ; U2.25@4214.96,945.62 U2.25@4224.34,945.62
RST_CTRL_51: R19.1 R20.1 U2.41 | length 451.6
  Top Layer w10: U2.41@4066.21,1223.13 4066.21,1263.29 4092.92,1290 4218.66,1290 4244.96,1316.3 R20.1@4244.96,1457 ; R19.1@4189.96,1457 R20.1@4244.96,1457 ; R20.1@4259.96,1457 R20.1@4244.96,1457
RST_CTRL_ARM: R23.1 R24.1 U2.40 | length 474.1
  Top Layer w10: U2.40@4085.89,1223.13 4085.89,1256.14 4097.76,1268 4231.66,1268 4269.96,1306.3 4269.96,1391.3 R23.1@4327.42,1448.76 ; R23.1@4329.96,1457 R24.1@4399.96,1457
SWD_SCL_DIR: R63.2 U2.29 U9.5 | length 1149.4
  Top Layer w8: v2@3986.42,1164.5 4020.92,1130 4062.92,1130 4168.56,1024.36 U2.29@4205.42,1024.36
  Top Layer w10: R63.2@3918.92,1869 R63.2@3924.92,1875 ; R63.2@3919.92,1883 R63.2@3920.15,1882.64 ; R63.2@3922.39,1879.04 R63.2@3920.15,1882.64 ; R63.2@3922.85,1875 R63.2@3924.92,1875 ; v2@3941.85,1875 3939.92,1875 R63.2@3924.92,1875 ; U9.5@3993.9,1919.53 3957.03,1919.53 3928.71,1891.21 R63.2@3920.15,1882.64
  Bottom Layer w10: v2(3939.92,1880) 3939.92,1764.49 3980.92,1723.49 3980.92,1495 ; 3980.92,1505 3980.92,1495 ; v2@3990.92,1160 3986.42,1164.5 3980.92,1170 3980.92,1495
  other v2: 3985.92,1164
SWD_SDA_DIR: R62.2 U2.24 U8.5 | length 1381.2
  Top Layer w8: v2(3953.92,1175) 3953.92,1161 4004.92,1110 4058.92,1110 4140.92,1028 4140.92,927 4144.95,922.97 U2.24@4144.95,885.65
  Top Layer w10: v2@3909.92,1925 R62.2@3909.92,1951 ; R62.2@3911.92,1951 R62.2@3914.92,1951 ; R62.2@3914.92,1957 3914.92,1955 R62.2@3914.92,1951 ; U8.5@3993.9,2049.53 3969.45,2049.53 3959.92,2040 3959.92,1975 3935.92,1951 R62.2@3914.92,1951
  Bottom Layer w10: v2(3914.92,1925) 3914.92,1760 3958.92,1716 3958.92,1485 ; v2@3958.92,1175 3958.92,1485 ; 3958.92,1505 3958.92,1485
TOOL_OPTION0: R2.1 U2.5 | length 121.1
  Top Layer w10: R2.1@3747.96,1080 3751.88,1083.92 U2.5@3867.44,1083.92
TOOL_OPTION1: R3.1 U2.6 | length 142.8
  Top Layer w10: R3.1@3746.46,1011.54 3799.15,1064.23 U2.6@3867.44,1064.23
TOOL_OPTION2: R28.1 U2.7 | length 191.4
  Top Layer w10: R28.1@3750.96,928.74 3784.96,962.74 3784.96,1008.74 3820.77,1044.55 U2.7@3867.44,1044.55
USBOK: D2.2 U2.21 | length 605
  Top Layer w10: D2.2@3760.51,532.47 3813.04,585 3982.22,585 4107.59,710.37 4107.59,811.43 4085.89,833.13 U2.21@4085.89,885.65
VCC3: C67.1 C74.1 R32.2 R92.1 R93.1 U5.8 U10.1 | length 756.7
  Top Layer w20: R32.2@1679.92,1175 R93.1@1679.92,1105 C67.1@1749.92,1105 C67.1@1749.92,1100 ; U5.8@1729.92,1025 U5.8@1749.92,1025 ; C67.1@1748.92,1100 C67.1@1749.92,1100 ; v2@1776.08,1100 C67.1@1749.92,1100 ; R92.1@1829.92,1035 1827.42,1032.5 1819.92,1025 U5.8@1749.92,1025 ; U5.8@1749.92,1025 C67.1@1749.92,1100
  Top Layer w30: v2(2074.92,1095) 2089.92,1110 C74.1@2089.92,1125 U10.1@2089.92,1195.31
  Bottom Layer w30: v2(1776.08,1095) v2(2074.92,1095)
VCC_USB: C2.1 D14.1 J1.A4 J1.A9 J1.M5 J1.M6 Q1.2 R1.1 | length 1456.2
  Top Layer w22: J1.A4@4393.76,634.61 4477.17,634.61 4506.59,634.61 ; J1.A9@4393.76,823.62 4477.17,823.62 4545.51,823.62
  Top Layer w30: 4506.59,634.61 4545.51,673.54 4545.51,823.62 4545.51,955 4594.84,1004.33 4594.84,1381.26 4594.84,1446.88 ; Q1.2@4544.96,1460 4596.96,1460 ; R1.1@4609.96,1457 R1.1@4619.96,1457 4651.92,1457 4669.92,1475 D14.1@4669.92,1698.39
VCP_OPTION: J3.1 U2.8 | length 845.4
  Top Layer w10: v2(3604.92,890) 3629.96,890 ; 3729.96,890 3629.96,890 ; U2.8@3867.44,1024.86 3831.08,1024.86 3814.96,1008.74 3814.96,913.74 3791.22,890 3629.96,890
  Bottom Layer w12: J3.1@3504.96,560 3504.96,790.04 v2(3604.92,890)
VDD: C12.1 J2.2 J6.4 R4.1 R6.1 R9.1 R10.1 R11.1 R12.1 R13.1 R14.2 R40.2 R41.2 SW1.2 U8.1 U9.1 | length 5168.8
  Top Layer w12: R11.1@3919.7,279.52 3920.22,279 3945.51,253.71 3945.86,253.36 ; 3945.87,251.65 3972.03,277.81 ; U9.1@4114.92,1860.47 4114.92,1795 4154.92,1755 4219.92,1755 4252.92,1788 R40.2@4252.92,1800 ; U8.1@4115.94,1990.47 4129.45,1990.47 4134.92,1985 4134.92,1945 ; 4134.92,1955 4134.92,1945 ; R40.2@4252.92,1798 R40.2@4252.92,1800 ; R40.2@4252.92,1805 R40.2@4252.92,1800 ; R40.2@4252.92,1815 4187.42,1880.5 4186.92,1881 4186.92,1890 4186.92,1893 4134.92,1945 ; R4.1@4269.92,2025 4309.92,1985 4309.92,1863.83 4252.92,1806.83 R40.2@4252.92,1800
  Top Layer w20: 3945.51,279 3945.51,253.71 3945.51,135 3985.51,95 4240.51,95 4304.96,159.45 J6.4@4304.96,180 4304.96,384.55 4265.51,424 C12.1@4265.51,430.79
  Top Layer w30: v4(3620.51,280) R6.1@3760.51,280 ; 3714.92,1645 3822.91,1537.01 v5@3822.91,1525 ; 3714.92,1645.64 3714.92,1905 ; R6.1@3760.51,279 3910.51,279 3920.22,279 3945.51,279 R9.1@4060.51,279 ; R12.1@3764.92,1866 3764.92,1905 ; R13.1@3764.92,1944 3764.92,1905 ; v5@3837.17,1524.26 3864.92,1524.26 R10.1@3934.92,1524.26 ; 4239.92,2150 SW1.2@4239.92,2250 ; R4.1@4263.92,2020 4263.92,2071 4217.42,2117.5 ; J2.2@4386.34,2150 4249.92,2150 4217.42,2117.5 ; 3714.92,1905 3764.92,1905 ; 3714.92,1905 3714.92,2045 3744.92,2075 3904.92,2075 3939.92,2110 4209.92,2110 4217.42,2117.5
  Bottom Layer w30: v4(3620.51,280) 3620.51,405 3680.51,465 3680.51,1185.55 3827.91,1332.95 v5(3827.91,1525)
VDD3: C5.1 J2.3 U1.1 | length 238.5
  Top Layer w40: J2.3@4386.34,2249.69 4412.6,2275.94 C5.1@4516.3,2275.94 ; U1.1@4516.3,2184.06 C5.1@4516.3,2275.94 ; C5.1@4522.09,2275.94 C5.1@4516.3,2275.94
VDD5: C4.1 D1.2 J2.1 U1.3 | length 287.7
  Top Layer w40: J2.1@4384.86,2048.21 4437.13,1995.94 4511.3,1995.94 U1.3@4511.3,2065.94 ; D1.2@4509.92,1901.61 C4.1@4509.92,1971.26
VDUT: C17.1 C54.1 C57.1 C73.1 C75.1 C76.1 CN1.19 CN1.39 CN1.67 CN1.109 D5.2 D13.1 J4.3 J7.3 J11.1 J11.2 J11.3 J11.4 J17.3 J19.1 JP3.1 Q2.2 R7.1 R44.2 R45.2 R58.2 R82.1 R83.1 TC2.1 U6.8 U8.8 U9.8 U10.3 U12.3 U12.5 UP2.3 | length 15331.4
  Top Layer w12: U8.8@3993.9,1990.47 4019.45,1990.47 4029.92,1980 4029.92,1833 C17.1@4001.92,1805 ; U9.8@3999.92,1860.47 3999.92,1805 C17.1@4000.92,1804
  Top Layer w15: v5@3624.92,1660.64 3624.92,1660 3624.92,1292 R7.1@3676.92,1240
  Top Layer w20: v4@2324.92,2170 2548.11,2170 v4(2568.11,2150) ; R58.2@2999.96,986.61 v4(2999.96,1020)
  Top Layer w24: 140.63,1640 C57.1@224.41,1640 U12.5@290.63,1640 ; U12.3@345.63,1883.09 345.63,1997.81 v4(345.63,2031.26) 345.63,2071.26 R83.1@409.37,2071.26
  Top Layer w25: C75.1@2269.92,1185 C73.1@2269.92,1125 2269.92,1075 2289.92,1055 ; 2279.92,1065 2289.92,1055 ; U6.8@2369.92,1055 2289.92,1055 ; U6.8@2379.92,1055 2379.92,1125 2379.92,1195 R45.2@2379.92,1200
  Top Layer w30: J19.1@109.92,1295 114.92,1300 130.63,1315.71 v4(130.63,2031.26) 130.63,2216.22 509.41,2595 3069.92,2595 3089.96,2574.96 C76.1@3089.96,2220 ; U10.3@2199.92,1195 2203.94,1195 C75.1@2269.92,1195 2269.92,1220 v5(2254.92,1235) ; JP3.1@2289.37,1530 2500.63,1530 v5(2554.37,1476.26) ; D13.1@3099.17,1598.74 3239.96,1598.74 ; J11.1@3204.96,1908.74 J11.2@3204.96,2008.74 ; J7.3@3304.96,1548.74 3299.96,1553.74 J7.3@3294.96,1558.74 ; J11.4@3304.96,2008.74 J11.3@3304.96,1908.74 3234.96,1908.74 3234.96,1618.74 J7.3@3294.96,1558.74 ; J4.3@3504.96,1558.74 J7.3@3304.96,1558.74 J7.3@3294.96,1558.74 ; v5@3629.89,1660.03 3644.92,1675.06 3644.92,2215 3738.98,2309.06 3799.02,2309.06 3805.75,2315.79 3826.57,2336.61 4321.57,2336.61 J17.3@4444.96,2460 ; v5(3809.92,1675) 3860.95,1675 Q2.2@3892.92,1706.97 ; Q2.2@3889.91,1709.98 C17.1@3979.92,1800 ; C17.1@3994.92,1800 C17.1@4001.92,1800
  Top Layer w40: 2994.41,2220 3000.92,2220 v5(3034.41,2220) C76.1@3089.96,2220 ; TC2.1@3089.96,2075 3089.96,2090 C76.1@3089.96,2205
  Top Layer w50: TC2.1@3049.92,2105 3054.67,2100.26 3146.18,2008.74 J11.2@3204.96,2008.74 J11.4@3304.96,2008.74
  Bottom Layer w20: CN1.109@759.92,1255 809.92,1205 904.92,1205 ; CN1.19@1959.92,455 2009.92,505 2009.92,985 ; CN1.67@2159.92,2455 2159.92,2435 2209.92,2385 2209.92,2330 2324.92,2215 v4@2324.92,2170 ; 2609.92,1205 2709.92,1205 CN1.39@2759.92,1155 ; CN1.39@2759.92,1150 2869.96,1150 v4(2999.96,1020)
  Bottom Layer w24: v4@130.63,2031.81 v4@330.63,2031.81
  Bottom Layer w30: 904.92,1205 1124.92,985 2009.92,985 2174.28,985 2254.37,1065.09 2254.37,1126.26 ; 2252.78,1127.85 2254.37,1129.45 2254.37,1235 2254.37,1530 JP3.1@2254.37,1535 ; J4.3@3506.81,1556.89 3507.44,1557.52 3619.92,1670 3624.92,1675 3629.92,1675 v5(3809.92,1675)
  Bottom Layer w40: 2612.15,1207.22 2559.37,1260 2559.37,1476.26 2559.37,2150 2559.37,2161.26 2619.37,2221.26 v5@3034.41,2221.26
  other v4: 2324.92,2165
  other v5: 3629.92,1660
XIN/MG_PC13: C19.1 CN1.68 U4.47 X1.2 | length 734.6
  Top Layer w8: U4.47@1683.78,1855.35 1683.78,1902.94 1742.85,1962.01 1795.12,1962.01 C19.1@1829.37,1996.26 1969.37,2136.26 1969.37,2144.45 1978.86,2153.94 2159.92,2335 CN1.68@2159.92,2355 ; C19.1@1829.37,1986.26 C19.1@1834.37,1991.26
XOUT/MG_PC14: C59.1 CN1.70 U4.48 X1.1 | length 691.4
  Top Layer w8: U4.48@1668.03,1855.35 1668.03,1914.92 C59.1@1749.37,1996.26 1790.94,2037.83 1790.94,2136.26 1841.18,2136.26 CN1.70@2059.92,2355
pads on no net: CN1.1 CN1.15 CN1.16 CN1.18 CN1.20 CN1.25 CN1.26 CN1.30 CN1.31 CN1.38 CN1.43 CN1.45 CN1.46 CN1.47 CN1.48 CN1.51 CN1.52 CN1.60 CN1.71 CN1.72 CN1.74 CN1.77 CN1.79 CN1.80 CN1.88 CN1.89 CN1.90 CN1.91 CN1.101 CN1.102 CN1.103 CN1.104 CN1.105 CN1.106 CN1.108 CN1.110 CN1.111 CN1.112 CN1.113 CN1.121 CN1.122 J1.A8 J1.B8 J6.6 J7.1 U2.1 U2.2 U2.3 U2.4 U2.28 U2.30 U2.32 U2.37 U2.38 U2.39 U2.46 U8.3 U8.6 U9.3 U9.6

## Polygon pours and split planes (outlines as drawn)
GND on Top Layer "Top Layer-No Net" (hatched 90Degree grid 10 track 10, remove dead copper, pour order 1000): 49.92,685 559.92,685 619.92,745 619.92,2575 579.92,2615 459.92,2615 119.92,2275 29.92,2185 29.92,705
GND on Top Layer "Top Layer-No Net" (hatched 90Degree grid 10 track 10, remove dead copper, pour order 1001): 654.92,20 4699.92,20 4699.92,2593.74 654.92,2593.74
GND on Bottom Layer "Top Layer-No Net" (hatched 90Degree grid 10 track 10, remove dead copper, pour order 1001): 49.92,685 559.92,685 619.92,745 619.92,2552.94 587.86,2585 429.92,2585 29.92,2185 29.92,705
GND on Bottom Layer "Top Layer-No Net" (hatched 90Degree grid 10 track 10, remove dead copper, pour order 1001): 654.92,20 4699.92,20 4699.92,2593.74 654.92,2593.74

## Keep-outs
Top Layer:
  circle w5: c814.41,2360 r59.06
  circle w5: c449.92,135 r59.06
  circle w5: c4625.51,421.9 r59.06
Keep-Out Layer:
  circle w7.88: c137.8,2500 r118.11
  circle w7.88: c3245.51,2500 r118.11
  circle w7.88: c3248.03,137.8 r118.11
  circle w7.88: c137.8,137.8 r118.11
  lines w15: 0,0 0,2637.8 3383.31,2637.8 3383.31,1678.74 3426.61,1678.74 ; 3383.31,0 3383.31,938.74 3426.61,938.74 ; 4724.41,1.26 4724.41,2639.06 4724.41,1.26

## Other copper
Top Layer:
  pour cut-out: 3339.92,2623.74 3459.92,2623.74 3459.92,0 3339.92,0
Bottom Layer:
  pour cut-out: 3339.92,2625 3459.92,2625 3459.92,0 3339.92,0

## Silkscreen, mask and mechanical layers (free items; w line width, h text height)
Top Overlay:
  circle w10: c137.8,2500 r137.8
  circle w10: c3245.51,2500 r137.8
  circle w4: c3248.03,137.8 r137.8
  circle w10: c137.8,137.8 r137.8
  region: 3150.87,947.11 3197.78,921.46 3195.87,937.11 3245.87,937.11 3245.87,957.11 3195.87,957.11 3197.78,971.46
  region: 3244.32,1059.29 3197.42,1084.94 3199.32,1069.29 3149.32,1069.29 3149.32,1049.29 3199.32,1049.29 3197.42,1034.94
  region: 1064.72,235.63 1090.57,271.9 1074.92,270 1074.92,320 1054.92,320 1054.92,270 1040.57,271.9
  region: 3507.04,264.05 3532.69,335.95 3517.04,334.05 3517.04,394.05 3497.04,394.05 3497.04,334.05 3482.69,335.95
  region: 3560.91,955.86 3607.82,930.21 3605.91,945.86 3634.96,945.86 3634.96,965.86 3605.91,965.86 3607.82,980.21
  region: 3634.36,1068.04 3587.46,1093.69 3589.36,1078.04 3559.96,1078.04 3559.96,1058.04 3589.36,1058.04 3587.46,1043.69
  lines w6: 954.92,2229.67 954.92,1955.64 1039.92,1870.64 1039.92,1795 1379.92,1795 1489.16,1904.24 1594.28,1904.24 1594.28,2304.36 ; 954.92,2290.64 954.92,2305 1019.86,2305
  lines w15: 789.53,-36.22 789.53,282.8 859.41,282.8 ; 2014.41,282.8 3151.73,282.8 3151.73,-35
  text "System Power" at 2689.86,2585 h45
  text "When J16 Open" at 3449.92,2580 h45
  text "SW1 must be off" at 3449.92,2520.64 h45
  text "PD6" at 1174.92,2515 h30 r90
  text "PD4" at 1274.92,2515 h30 r90
  text "PD2" at 1374.92,2515 h30 r90
  text "PD0" at 1474.92,2515 h30 r90
  text "PE14" at 1774.92,2515 h30 r90
  text "PE12" at 1874.92,2515 h30 r90
  text "GND" at 2074.96,2515 h30 r90
  text "VDUT" at 2174.96,2515 h30 r90
  text "PC11" at 2274.92,2515 h30 r90
  text "PC9" at 2374.92,2515 h30 r90
  text "PC7" at 2434.41,2515 h30 r90
  text "RST" at 4049.86,2415 h37 r90
  text "GND" at 4099.86,2415 h37 r90
  text "Power" at 4014.92,2350 h45
  text "Off" at 3880.82,2348.32 h45
  text "On" at 4234.92,2345 h45
  text "5V" at 3079.86,2335 h45
  text "SCL" at 4559.92,2325 h35 r90
  text "CLK" at 4664.92,2325 h35 r90
  text "SDA" at 4369.86,2320 h37 r90
  text "VCC" at 4459.92,2320 h37 r90
  text "PD3" at 1314.92,2265 h30
  text "PD1" at 1429.92,2265 h30
  text "PE13" at 1713.38,2260.51 h30
  text "PC14" at 2014.41,2260 h30
  text "PD5" at 1284.41,2213.97 h30 r90
  text "PC8" at 2474.41,2210 h30 r90
  text "VDD3" at 4324.92,2195 h37 r90
  text "PC13" at 2169.92,2185 h30 r90
  text "PC12" at 2234.41,2185 h30 r90
  text "PC10" at 2374.41,2185 h30 r90
  text "PE15" at 1669.41,2183.97 h30 r90
  text "PD7" at 949.41,2160 h30 r90
  text "PC6" at 2824.92,2136 h30
  text "VDD" at 4234.92,2115 h37
  text "VDUT" at 3189.41,2070 h35
  text "VDD5" at 4204.92,2060 h37
  text "PC4" at 2824.92,2036 h30
  text "PD8" at 609.92,2035 h30
  text "PC5" at 2509.92,2035 h30
  text "PD9" at 949.41,2030 h30 r90
  text "PC3" at 2509.92,1940 h30
  text "PC2" at 2824.92,1936 h30
  text "PD10" at 584.41,1935 h30
  text "RESET" at 2204.41,1905 h30 r90
  text "PD11" at 949.41,1895 h30 r90
  text "LCD Cap. Ext." at 1094.92,1870 h40
  text "PD13" at 923.9,1840 h30
  text "PC1" at 2509.92,1840 h30
  text "PC0" at 2824.92,1836 h30
  text "PD12" at 584.41,1835 h30
  text "R-Ladder" at 1094.92,1810 h40
  text "PD15" at 923.9,1740 h30
  text "PD14" at 584.41,1735 h30
  text "Power" at 3039.41,1705 h35
  text "SCL" at 3164.41,1645 h33
  text "PE9" at 2509.92,1640 h30
  text "PE8" at 2824.92,1640 h30
  text "CAN XCVR" at 139.86,1595 h45 r90
  text "VDUT" at 3134.41,1515 h33
  text "SDA" at 3159.41,1440 h33
  text "LDO-3.3V" at 2014.92,1410.64 h40
  text "VDUT" at 59.86,1370 h30
  text "GND" at 3159.41,1340 h33
  text "GND" at 609.92,1335 h30
  text "PB15" at 2494.92,1335 h30
  text "VDUT" at 579.41,1240 h30
  text "RST" at 3164.41,1240 h33
  text "GND" at 2819.96,1238.74 h30
  text "PB14" at 2494.92,1235 h30
  text "H" at 169.86,1185 h30
  text "VDUT" at 2819.96,1138.74 h30
  text "PB13" at 2489.92,1135 h30
  text "PB8_TX" at 3164.96,1128.74 h38
  text "L" at 169.92,1090.64 h30
  text "SPI Flash" at 1174.92,1070.64 h45
  text "PB12" at 2824.96,1043.74 h30
  text "PA0" at 924.41,1035 h30
  text "PB10" at 2824.96,943.74 h30
  text "PA1" at 599.41,935 h30
  text "PA2" at 924.41,935 h30
  text "PB11" at 2594.92,910 h30 r90
  text "GND" at 69.86,905 h30
  text "PB8" at 2824.96,843.74 h30
  text "PA3" at 599.41,840 h30
  text "PB9_RX" at 3164.41,840 h38
  text "PA4" at 924.41,835 h30
  text "PB9" at 2514.92,826.07 h30
  text "I2C EEPROM" at 1999.92,815 h45
  text "PB7" at 2514.96,743.74 h30
  text "PA6" at 924.41,740 h30
  text "PA5" at 599.41,730 h30
  text "PA7" at 1084.96,618 h30 r90
  text "PA9" at 1174.96,618 h30 r90
  text "PA11" at 1274.96,618 h30 r90
  text "PA13" at 1374.96,618 h30 r90
  text "PA15" at 1474.96,618 h30 r90
  text "PB1" at 1579.96,618 h30 r90
  text "PB3" at 1679.96,618 h30 r90
  text "PE1" at 2074.96,618 h30 r90
  text "PE3" at 2174.96,618 h30 r90
  text "PB5" at 2374.96,618 h30 r90
  text "GND" at 3199.86,610 h35
  text "2024.12" at 646.92,459.64 h35
  text "TH273A_MG32F02N128" at 24.92,385 h50
  text "LCD_P1" at 929.86,325 h30
  text "PE0" at 2079.41,310 h30 r90
  text "PE2" at 2179.41,310 h30 r90
  text "PB4" at 2379.96,310 h30 r90
  text "PB6" at 2479.96,310 h30 r90
  text "GND" at 1879.41,305 h30 r90
  text "STN LCD Module IF" at 2579.92,305 h45
  text "PA8" at 1174.96,301.54 h30 r90
  text "PB0" at 1579.96,301.54 h30 r90
  text "PB2" at 1679.96,301.54 h30 r90
  text "LQFP80_EV_V11" at 24.92,295 h45
  text "PA10" at 1274.41,280 h30 r90
  text "PA12" at 1374.41,280 h30 r90
  text "PA14" at 1474.41,280 h30 r90
  text "VDUT" at 1979.41,280 h30 r90
  text "+VDD" at 883.48,240.53 h35
  text "3" at 1134.92,235 h30
  text "5" at 1213.66,235 h30
  text "7" at 1292.4,235 h30
  text "9" at 1371.14,235 h30
  text "11" at 1444.92,235 h30
  text "13" at 1519.92,235 h30
  text "15" at 1598.66,235 h30
  text "17" at 1677.4,235 h30
  text "19" at 1756.14,235 h30
  text "21" at 1834.88,235 h30
  text "G" at 1923.62,235 h30
  text "23" at 1982.36,235 h30
  text "25" at 2061.1,235 h30
  text "27" at 2139.84,235 h30
  text "29" at 2218.58,235 h30
  text "31" at 2297.32,235 h30
  text "33" at 2376.06,235 h30
  text "35" at 2454.8,235 h30
  text "37" at 2533.54,235 h30
  text "39" at 2612.28,235 h30
  text "41" at 2691.02,235 h30
  text "43" at 2769.76,235 h30
  text "GND" at 2854.92,235 h30
  text "J3" at 3464.96,201.9 h45
  text "Open Disable VCP." at 3445.51,130 h40
  text "Open Disable VCP." at 3445.51,130 h40
  text "Short Enable VCP." at 3445.51,35 h40
  text "Short Enable VCP." at 3445.51,35 h40
  text "LCD_P0" at 914.92,20 h30
  text "2" at 1133.66,20 h30
  text "4" at 1212.4,20 h30
  text "6" at 1291.14,20 h30
  text "8" at 1369.88,20 h30
  text "10" at 1439.92,20 h30
  text "12" at 1519.92,20 h30
  text "14" at 1598.66,20 h30
  text "16" at 1677.4,20 h30
  text "18" at 1756.14,20 h30
  text "20" at 1834.88,20 h30
  text "G" at 1923.62,20 h30
  text "22" at 1982.36,20 h30
  text "24" at 2061.1,20 h30
  text "26" at 2139.84,20 h30
  text "28" at 2218.58,20 h30
  text "30" at 2297.32,20 h30
  text "32" at 2376.06,20 h30
  text "34" at 2454.8,20 h30
  text "36" at 2533.54,20 h30
  text "38" at 2612.28,20 h30
  text "40" at 2691.02,20 h30
  text "42" at 2769.76,20 h30
  text "GND" at 2848.7,20 h30
Mechanical 1:
  circle w7.88: c3404.96,1008.74 r33
  circle w7.88: c3404.96,1298.74 r25
  circle w7.88: c3404.96,1416.74 r25
  circle w7.88: c3404.96,1503.74 r27
  circle w7.88: c3404.96,1613.74 r27
  lines w7.88: 3383.31,1078.74 3426.61,1078.74 3426.61,1232.74 3383.31,1232.74 3383.31,1078.74
  lines w8.88: 4724.41,0 3426.61,0 3426.61,938.74 3383.31,938.74 3383.31,0 0,0 0,2637.8 3383.31,2637.8 3383.31,1678.74 3426.61,1678.74 3426.61,2637.8 4724.41,2637.8 ; 4724.41,0 4724.41,2637.8 ; 4724.41,0 4724.41,2637.8
Mechanical 2:
  lines w6: 3404.96,1031.74 3404.96,1008.74 3427.96,1008.74 ; 3404.96,1321.74 3404.96,1298.74 3427.96,1298.74 ; 3404.96,1441.74 3404.96,1418.74 3427.96,1418.74 ; 3404.96,1526.74 3404.96,1503.74 3427.96,1503.74 ; 3404.96,1636.74 3404.96,1613.74 3427.96,1613.74

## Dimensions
0,0 to 4724.41,0 on Top Overlay
0,0 to 0,2637.8 on Top Overlay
